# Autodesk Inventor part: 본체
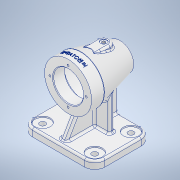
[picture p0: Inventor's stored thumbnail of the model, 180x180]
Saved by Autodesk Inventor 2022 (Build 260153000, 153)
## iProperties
Created: 2024-12
Part Number: 본체
Material: 알루미늄 6061
Document SubType Name: Modeling
Designer: PC-12
Density: 2.7 g/cm^3
Appearance: 알루미늄 - 평지
Mass: 739.323 g
Surface Area: 673.876 cm^2
Volume: 273.823 cm^3
Author: PC-12
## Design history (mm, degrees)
sketch "스케치1"
  geometry: L1 (0, -42)-(37, -42); L2 (37, -42)-(37, -22); L3 (37, -22)-(0, -22); L4 (0, -22)-(0, -42); L5 (37, -22)-(21, 42); L6 (21, 42)-(0, 42); L7 (0, 42)-(0, -22); L8 (-7.4, 0)-(44.4, 0) reference; 1 further point
  constraints: 14 end point, 2 horizontal, 2 parallel, 1 perpendicular, 1 point on line, 1 vertical, 1 other
  dimensions: "d0" = 74 diameter of L2 L4; "d1" = 84 distance between parallel lines of L6 L1; "d2" = 20 distance of L1.end L2.end; "d3" = 42 diameter of L5.end L7
revolve "회전1" sketch "스케치1" stored, may be unused: angle "d4" = 90 deg
node "작업 평면1"
sketch "스케치2"
  geometry: L1 (-57, 32)-(57, 32); L2 (57, 32)-(57, -57); L3 (57, -57)-(-57, -57); L4 (-57, -57)-(-57, 32); L5 (-21, 42)-(21, 42) reference; L6 (-37, -42)-(37, -42) reference; L7 (0, -90.26)-(0, 64.043) reference; 1 further point
  constraints: 8 end point, 2 parallel, 1 horizontal, 1 perpendicular, 1 other
  dimensions: "d6" = 89 distance of L3.end L1.start; "d7" = 114 distance of L2.end L3.end; "d8" = 15 distance between parallel lines of L6 L3
extrude "돌출1" join sketch "스케치2" distance "d9" = 12; taper "d10" = 0 deg
sketch "스케치3"
  geometry: L1 (28, -3)-(-28, -3); L2 (-28, -3)-(-28, 5); L3 (-28, 5)-(28, 5); L4 (28, 5)-(28, -3); L5 (28, -3)-(-28, 5); L6 (-28, -3)-(28, 5); L7 (-57, -32)-(57, -32) reference; L8 (0, 76.8)-(0, -61.8) reference; L9 (5, -32)-(-5, -32); L10 (-5, -32)-(-5, -3); L11 (-5, -3)-(5, -3); L12 (5, -3)-(5, -32); 5 further points
  constraints: 20 end point, 4 parallel, 3 midpoint, 3 point on line, 2 horizontal, 2 perpendicular, 1 other
  dimensions: "d11" = 29 distance between parallel lines of L7 L1; "d12" = 8 distance of L1.end L2.end; "d13" = 56 distance of L2.end L3.end; "d14" = 10 distance between parallel lines of L12 L10
extrude "돌출2" join sketch "스케치3" stored distance "d15" = 12; taper "d16" = 0 deg
sketch "스케치4"
  geometry: L1 (-70, 32)-(-70, -57) reference; L2 (-70, -50)-(0, -9.585); L3 (0, -76.8)-(0, 61.8) reference; L4 (-82, -57)-(-70, -57) reference; 1 further point
  constraints: 2 end point, 2 point on line
  dimensions: "d17" = 7 distance from line of L2.start L4; "d18" = 60 deg angle of L2 L1
feature "리브1" sketch "스케치4" dims "d19" = 1, "d20" = 10, "d21" = 0, "d22" = 0, "d23" = 1, "d24" = 1
sketch "스케치5" dims "d25" = 20
  geometry: L1 (-10, 14)-(10, 14); L2 (10, 14)-(10, -42); L3 (10, -42)-(-10, -42); L4 (-10, -42)-(-10, 14); L5 (-37, -42)-(37, -42) reference; L6 (0, 0)-(0, 14); 1 further point
  constraints: 10 end point, 3 vertical, 2 parallel, 1 collinear, 1 horizontal, 1 perpendicular, 3 other
  dimensions: "d26" = 56 distance between parallel lines of L1 L5
extrude "돌출3" join sketch "스케치5" distance "d27" = 33; taper "d28" = 0 deg
fillet "모깎기1" dims "d29" = 16
sketch "스케치6"
  geometry: A1 r 16 centre (41, 41) between (57, 41) and (41, 57) reference; A2 r 16 centre (41, -16) between (41, -32) and (57, -16) reference; A3 r 16 centre (-41, -16) between (-57, -16) and (-41, -32) reference; A4 r 16 centre (-41, 41) between (-41, 57) and (-57, 41) reference; 5 further points
  constraints: 4 coincident
hole "구멍1" sketch "스케치6" at (41, 41), (41, -16), (-41, -16), (-41, 41) diameter "d30" = 9; stored, may be unused: countersink angle "d34" = 90 deg, drill point angle "d36" = 118 deg; dims "d31" = 8, "d32" = 24, "d33" = 2, "d35" = 10
sketch "스케치7"
  geometry: L1 (-37, -42)-(37, -42) reference; L2 (23.5, -42)-(0, -42); L3 (0, -42)-(0, -24); L4 (0, -24)-(23.5, -24); L5 (23.5, -24)-(23.5, -42); L6 (-21, 42)-(21, 42) reference; L7 (0, -24)-(0, 21); L8 (23.5, -24)-(32.346, -24); L9 (32.346, -24)-(21.096, 21); L10 (21, 42)-(37, -22) reference; L11 (0, 21)-(17.5, 21); L12 (17.5, 21)-(17.5, 31); L13 (17.5, 31)-(0, 31); L14 (0, 31)-(0, 21); L15 (21.096, 21)-(17.5, 21); L16 (0, 31)-(15.5, 31); L17 (15.5, 31)-(15.5, 34); L18 (15.5, 34)-(0, 34); L19 (0, 34)-(0, 31); 2 further points
  constraints: 32 end point, 7 parallel, 5 horizontal, 3 perpendicular, 2 point on line, 1 vertical
  dimensions: "d37" = 18 distance of L4.end L2.start; "d38" = 47 diameter of L5 L3; "d41" = 5 distance between parallel lines of L10 L9; "d42" = 45 distance between parallel lines of L11 L4; "d43" = 35 diameter of L12 L14; "d44" = 31 diameter of L17 L19; "d45" = 10 distance of L11.end L12.end; "d46" = 3 distance of L16.end L17.end
revolve "회전2" sketch "스케치7" stored, may be unused: angle "d47" = 90 deg
sketch "스케치8"
  geometry: A1 r 10 centre (0, -14) between (-10, -14) and (10, -14) reference; 2 further points
  constraints: 1 coincident
hole "구멍2" sketch "스케치8" at (0, -14) diameter "d48" = 5.1881; stored, may be unused: countersink angle "d52" = 90 deg, drill point angle "d54" = 0 deg; dims "d49" = 100, "d50" = 10, "d51" = 1, "d53" = 8
sketch "스케치9"
  geometry: L1 (0, 0)-(0, 28.5)
  constraints: 2 end point, 1 vertical
  dimensions: "d55" = 28.5 distance of L1.start L1.end
hole "구멍3" sketch "스케치9" at (0, 28.5) diameter "d56" = 3.242; stored, may be unused: countersink angle "d60" = 90 deg, drill point angle "d62" = 118 deg; dims "d57" = 8, "d58" = 10, "d59" = 1, "d61" = 10
node "작업 평면2"
sketch "스케치10"
  geometry: L1 (-21.075, 2.002)-(21.075, 2.002); L2 (21.075, 2.002)-(21.075, -4.002); L3 (21.075, -4.002)-(-21.075, -4.002); L4 (-21.075, -4.002)-(-21.075, 2.002); L5 (-21.075, -1)-(21.075, -1); L6 (0, 2.002)-(0, -4.002); L7 (-37, -10)-(37, -10) reference; 1 further point
  constraints: 4 end point, 4 midpoint, 1 point on line, 2 other
  dimensions: "d66" = 9 distance between parallel lines of L5 L7
feature "엠보싱1" sketch "스케치10" dims "d0" = 74, "d1" = 84, "d2" = 20, "d3" = 42, "d67" = 0.5, "d68" = 0
fillet "모깎기2" dims "d69" = 0.3
fillet "모깎기3" dims "d70" = 5
fillet "모깎기4" dims "d71" = 3
chamfer "모따기1" distance "d72" = 1; stored, may be unused: second distance "d73" = 2, angle "d74" = 45 deg
fillet "모깎기5" dims "d75" = 3
fillet "모깎기6" dims "d76" = 3
fillet "모깎기7" dims "d77" = 3
fillet "모깎기8" dims "d78" = 3
fillet "모깎기9" dims "d79" = 3
fillet "모깎기10" dims "d80" = 3
fillet "모깎기11" dims "d81" = 3
node "솔리드1"
pattern_circular "원형 패턴1" dims angle "d64" = 360 deg
feature "A9D066F2-1C7D-4E18-AEED-F7BC21143FA4" dims "d30" = 9, "d31" = 8, "d32" = 24, "d33" = 2, "d34" = 90 deg, "d35" = 10, "d36" = 118 deg
other parameters: "d5" = -82
